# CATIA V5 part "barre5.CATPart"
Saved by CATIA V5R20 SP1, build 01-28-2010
Part number: barre5
Publications: "Plan.1", "G", "D", "axe_5_4", "axe_5_2"
Bounding box of the stored display mesh (mm): x -10 to 10, y -983.26 to -802.808, z 252.465 to 338.703
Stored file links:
  C:\Users\patrice\Desktop\IFMa\Semestre 3\IAO\projet iao\iao\barre5.CATPart
  C:\Users\patrice\Desktop\IFMa\Semestre 3\IAO\projet iao\iao\skl_iao_755.CATProduct
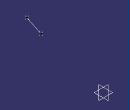
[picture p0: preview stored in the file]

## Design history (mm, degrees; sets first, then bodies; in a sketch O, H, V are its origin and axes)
Set1
  Plane1: linked copy from another document
  DatumPoint1 "G": linked copy from another document
  DatumPoint2 "D": linked copy from another document
Set2
  Plane2: type Offset, RefPlane Plane1, Offset 0
  Point1 "G": (0, 0, 0), relative to DatumPoint1
  Point2 "D": (0, 0, 0), relative to DatumPoint2
  Line1: type PtPt, FirstPoint Point1, SecondPoint Point2
  Line2 "axe_5_4": type Normal, RefPoint Point1, RefSkin Plane2, Start 0, End 10
  Line3 "axe_5_2": type Normal, RefPoint Point2, RefSkin Plane2, Start 0, End 10
Body1 (main body)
